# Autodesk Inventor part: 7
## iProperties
Created: 2012-03
Part Number: 7
Document SubType Name: Modeling
Designer: Administrator
Density: 7.85 g/cm^3
Material: Steel
Mass: 11.1038 g
Surface Area: 13.4117 cm^2
Volume: 1.4145 cm^3
Translation Standard: STEP AP203
FileName: //expscmdclustefs.cadenas.external/client_exchange/iodir/jobs/output/wkb42693478_no0/STEP/208_9001__24208_90010__2_03.stp
PostProcessor: Build: 236a, Release: 2009 RTM - Date: Fri 02/22/2008
Sent Units: CM
Uncertainty: 0.0
Author: Administrator
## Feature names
1. Base1
